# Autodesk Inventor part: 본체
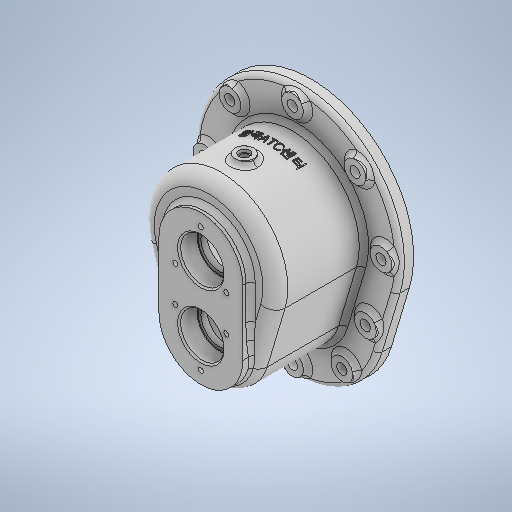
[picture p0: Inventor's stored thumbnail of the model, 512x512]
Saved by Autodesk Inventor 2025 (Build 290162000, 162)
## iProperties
Created: 2026-07
Part Number: 본체
Material: 알루미늄 6061
Document SubType Name: Modeling
Designer: KDI
Density: 2.7 g/cm^3
Appearance: 알루미늄 - 평지
Mass: 772.551 g
Surface Area: 806.209 cm^2
Volume: 286.13 cm^3
Sending System: Autodesk Inventor 2027
Preprocessor: ST-DEVELOPER v20.1
Author: jhkim
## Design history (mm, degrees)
feature "솔리드1"
node "솔리드2"
